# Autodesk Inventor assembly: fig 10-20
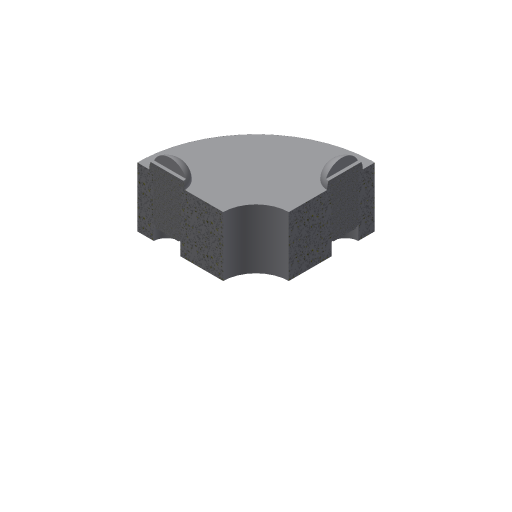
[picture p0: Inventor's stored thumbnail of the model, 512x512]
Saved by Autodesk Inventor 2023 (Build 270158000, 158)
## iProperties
Created: 2002-02
Part Number: fig 10-20
Document SubType Name: Assembly
Designer: ***
Control State: 0
Master: False
Checked Out: False
Shininess: 64.0
Angle Display Precision: 2
Document Length Units: 11269
Document Angle Units: 11279
Document Time Units: 11290
Document Mass Units: 11283
Document Length Units Precision: 3
Document Angle Units Precision: 2
Density: 0.0
Volumn: 0.0
Area: 0.0
PropertySet Name: Model Information
Author: ***
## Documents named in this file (3)
- D:\PROJECTS\Project 2022\Autodesk Inventor For Professional 2023\RESOURCES INVENTOR 2023\RESOURCES INVENTOR 2023\Inventor_2023_Part\Inventor_2023_Part\c10_Inv_2023_prt\fig 10-20.iam
- D:\PROJECTS\Project 2022\Autodesk Inventor For Professional 2023\RESOURCES INVENTOR 2023\RESOURCES INVENTOR 2023\Inventor_2023_Part\Inventor_2023_Part\c10_Inv_2023_prt\Screw.ipt
- D:\PROJECTS\Project 2022\Autodesk Inventor For Professional 2023\RESOURCES INVENTOR 2023\RESOURCES INVENTOR 2023\Inventor_2023_Part\Inventor_2023_Part\c10_Inv_2023_prt\test.ipt
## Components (6 placed, 2 different names)
1. test:1 — Insert:1, Insert:2
2. test:2 — Insert:1
3. Screw:1 — Angle:1, Insert:2
4. Screw:11
5. Screw:12
6. Screw:13
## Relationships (3: Insert 2, Angle 1)
- Insert:1: test:1 ↔ test:2
- Angle:1: Screw:1
- Insert:2: test:1 ↔ Screw:1
